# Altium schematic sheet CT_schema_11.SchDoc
size 389 x 278 mm
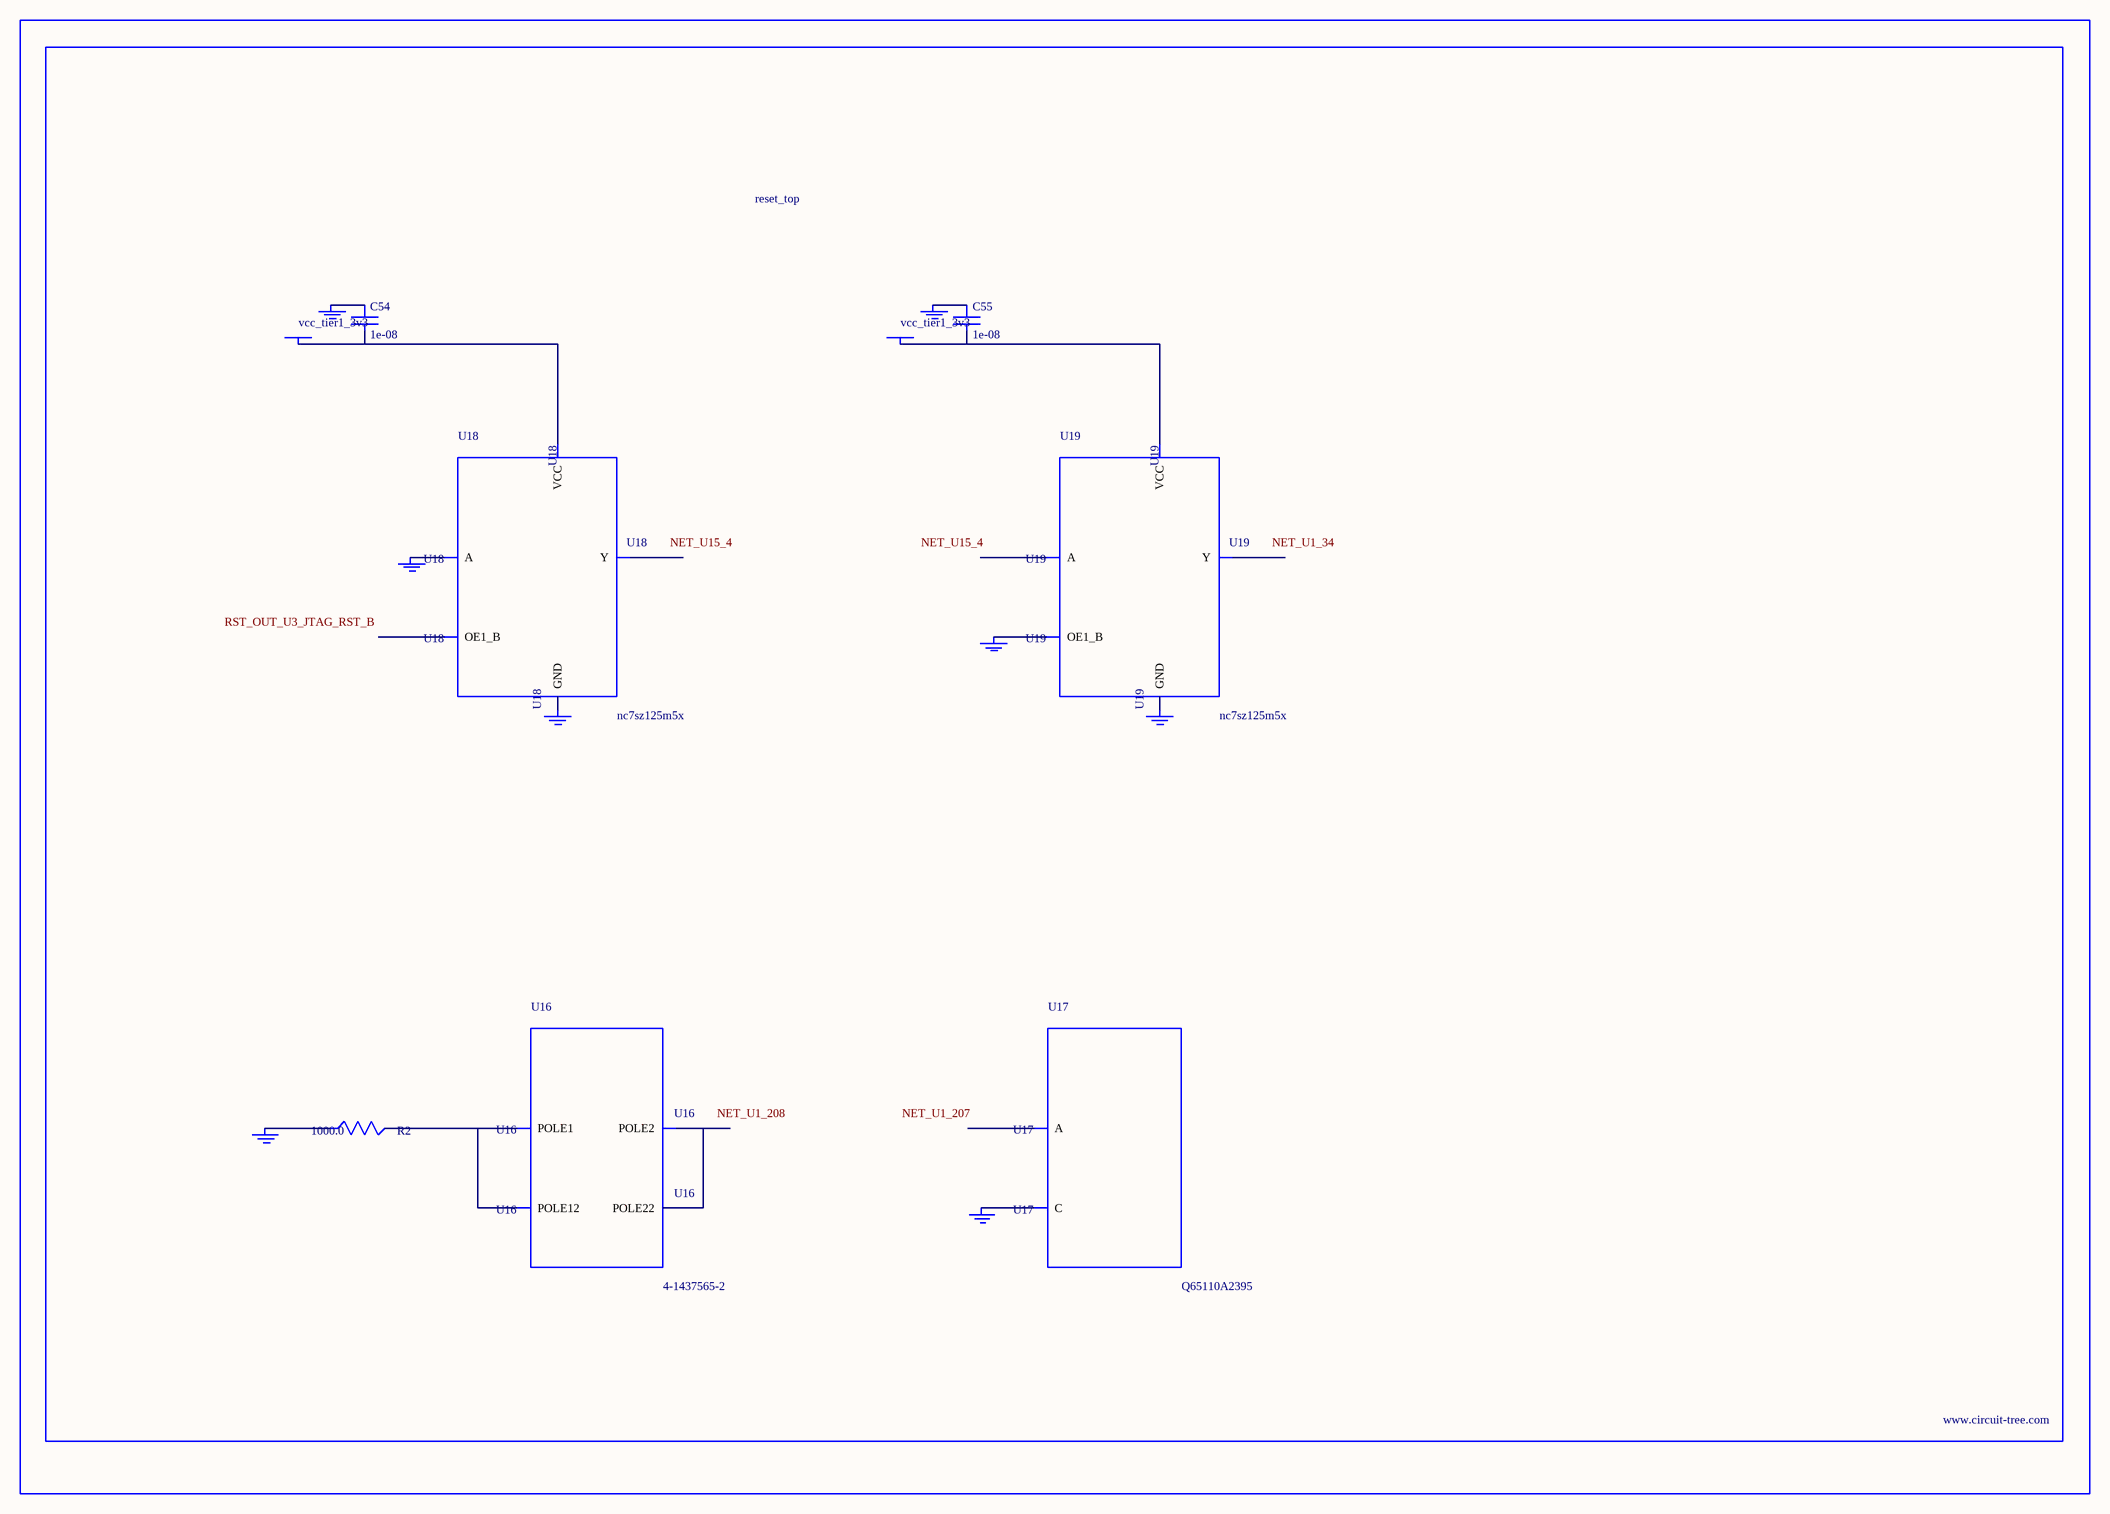
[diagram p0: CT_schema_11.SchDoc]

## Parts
BORDER10  (no value)
C54  1e-08  [C0402]
C55  1e-08  [C0402]
GND_INSTANCE_10_0  (no value)
GND_INSTANCE_10_1  (no value)
GND_INSTANCE_10_2  (no value)
GND_INSTANCE_10_3  (no value)
GND_INSTANCE_10_4  (no value)
GND_INSTANCE_10_5  (no value)
GND_INSTANCE_10_6  (no value)
GND_INSTANCE_10_7  (no value)
POWER_INSTANCE_10_0  vcc_tier1_3v3
POWER_INSTANCE_10_1  vcc_tier1_3v3
R2  1000.0  [R0603]
U16  4-1437565-2  [SW_4-1437565-2]
U17  Q65110A2395  [LGM67K-G1J2-24-Z]
U18  nc7sz125m5x  [NC7SZ125M5X]
U19  nc7sz125m5x  [NC7SZ125M5X]

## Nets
NetC54_1: C54.1 GND_INSTANCE_10_2.0(GND)
NetC54_2: C54.2 POWER_INSTANCE_10_0.0(PWR) U18.5(VCC)
NetC55_1: C55.1 GND_INSTANCE_10_5.0(GND)
NetC55_2: C55.2 POWER_INSTANCE_10_1.0(PWR) U19.5(VCC)
NetGND_INSTANCE_10_0_0: GND_INSTANCE_10_0.0(GND) R2.1
NetGND_INSTANCE_10_1_0: GND_INSTANCE_10_1.0(GND) U17.C
NetGND_INSTANCE_10_3_0: GND_INSTANCE_10_3.0(GND) U18.2(A)
NetGND_INSTANCE_10_4_0: GND_INSTANCE_10_4.0(GND) U18.3(GND)
NetGND_INSTANCE_10_6_0: GND_INSTANCE_10_6.0(GND) U19.1(OE1_B)
NetGND_INSTANCE_10_7_0: GND_INSTANCE_10_7.0(GND) U19.3(GND)
NetR2_2: R2.2 U16.1(POLE1) U16.2(POLE12)
NetU16_3: U16.3(POLE2) U16.4(POLE22)

Not connected (* = marked no-connect by the designer): U17 A; U18 1(OE1_B) 4(Y); U19 2(A) 4(Y)

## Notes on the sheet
- Labels drawn without touching a wire or pin: NET_U1_34, NET_U1_207, NET_U1_208, NET_U15_4, RST_OUT_U3_JTAG_RST_B

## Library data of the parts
BORDER10 = BORDER_PAGE10
C54 C55 = C0402C103K3RAC
GND_INSTANCE_10_0-GND_INSTANCE_10_7 = GND
POWER_INSTANCE_10_0 POWER_INSTANCE_10_1 = PWR
R2 = RC0603JR-071KL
